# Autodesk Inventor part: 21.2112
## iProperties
Created: 2012-10
Part Number: 21.2112
Document SubType Name: Modeling
Designer: Administrator
Density: 2.71 g/cm^3
Material: Aluminum-6061
Mass: 63.4152 g
Surface Area: 69.0711 cm^2
Volume: 23.4004 cm^3
Description: CONNECTING PLATE 30X60
Stock Number: 21.2112 CONNECTING PLATE 30X60
Translation Standard: STEP AP214IS
FileName: 21_2113_0_1.stp
PreProcessor: ACIS
PostProcessor: Build: 236a, Release: 2009 RTM - Date: Fri 02/22/2008
Sent Units: MM
Uncertainty: 1e-06
Author: Administrator
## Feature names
1. Base1
